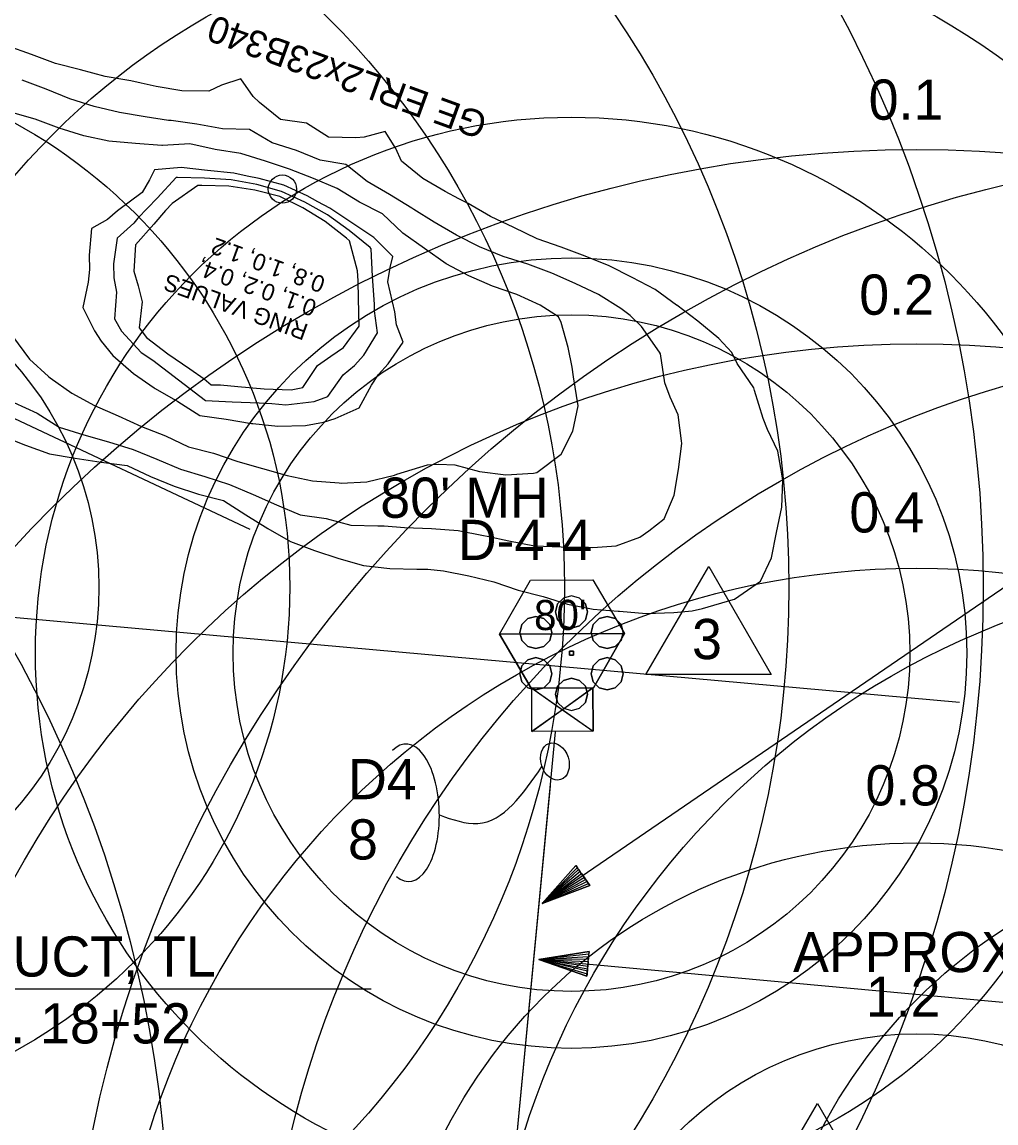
# Model space of a CAD drawing. Extents: x 1638506 to 1658005, y 834807 to 846788.
# Drawn here: x 1641616.9 to 1641907.6, y 842309.7 to 842638.4 of the extents above; entities that cross this region are included whole.
import ezdxf

# ---------------------------------------------------------------- set-up
doc = ezdxf.new("R2010")
doc.units = 0
for name, color, linetype in [('Default', 7, 'Continuous'), ('Old_Level_1', 7, 'Continuous'), ('Old_Level_2', 7, 'Continuous'), ('Old_Level_4', 7, 'Continuous'), ('Scratch_Level_0', 7, 'Continuous')]:
    doc.layers.add(name, color=color, linetype=linetype)

msp = doc.modelspace()

# ---------------------------------------------------------------- linework, layer by layer
at = {"layer": 'Default'}
for p, q in [((1642010.57, 842538.29), (1641772.14, 842375.26)), ((1641769.06, 842439.54), (1641787.43, 842426.69)), ((1641769.14, 842426.58), (1641787.35, 842439.65)), ((1641763.26, 842291.23), (1641776.21, 842426.53)), ((1641763.65, 842295.33), (1641774.67, 842410.42)), ((1641771.15, 842358.56), (1642042.57, 842333.49)), ((1641501.67, 842349.79), (1641721.14, 842349.79))]:
    msp.add_line(p, q, dxfattribs=at)
for points in [[(1641840.54, 842443.61), (1641803.15, 842443.61), (1641821.98, 842475.88)], [(1641759.43, 842455.63), (1641768.73, 842471.83), (1641787.31, 842471.94), (1641796.8, 842455.85)], [(1641759.43, 842455.63), (1641768.92, 842439.54), (1641787.5, 842439.65), (1641796.8, 842455.85)], [(1641759.43, 842455.63), (1641796.8, 842455.85), (1641787.5, 842439.65), (1641768.92, 842439.54)], [(1641769.06, 842439.54), (1641787.35, 842439.65), (1641787.43, 842426.69), (1641769.14, 842426.58)], [(1641778.25, 842433.11), (1641769.14, 842426.58), (1641769.06, 842439.54)], [(1641778.25, 842433.11), (1641787.43, 842426.69), (1641787.35, 842439.65)], [(1641872.96, 842283.3), (1641835.57, 842283.3), (1641854.4, 842315.57)]]:
    msp.add_lwpolyline(points, close=True, dxfattribs=at)
for points in [[(1641784.35, 842383.61), (1641784.77, 842383), (1641772.14, 842375.26), (1641785.16, 842382.43), (1641785.58, 842381.82), (1641772.14, 842375.26), (1641786, 842381.21), (1641786.41, 842380.6), (1641772.14, 842375.26), (1641782.23, 842386.63), (1641782.68, 842386.05), (1641772.14, 842375.26), (1641783.06, 842385.41), (1641783.52, 842384.83), (1641772.14, 842375.26), (1641783.94, 842384.22), (1641786.41, 842380.6), (1641782.23, 842386.63), (1641772.14, 842375.26), (1641786.41, 842380.6)], [(1641785.88, 842357.2), (1641785.81, 842356.46), (1641771.15, 842358.56), (1641785.75, 842355.78), (1641785.68, 842355.04), (1641771.15, 842358.56), (1641785.61, 842354.3), (1641785.54, 842353.57), (1641771.15, 842358.56), (1641786.17, 842360.89), (1641786.15, 842360.15), (1641771.15, 842358.56), (1641786.03, 842359.41), (1641786.02, 842358.67), (1641771.15, 842358.56), (1641785.95, 842357.94), (1641785.54, 842353.57), (1641786.17, 842360.89), (1641771.15, 842358.56), (1641785.54, 842353.57)]]:
    msp.add_lwpolyline(points, dxfattribs=at)
for start_param, end_param in [(1.570796, 3.572354), (5.884886, 7.853982)]:
    msp.add_ellipse((1641731.92, 842402.36), major_axis=(0.49, -20.52), ratio=0.466223, start_param=start_param, end_param=end_param, dxfattribs=at)
msp.add_ellipse((1641775.98, 842417.66), major_axis=(-1.72, 5.4), ratio=0.730797, dxfattribs=at)
msp.add_spline([(1641741.5, 842401.69), (1641752.96, 842399.12), (1641772.12, 842416.16)], degree=3, dxfattribs=at)
at = {"layer": 'Old_Level_1'}
for points in [[(1641610.87, 842514.93), (1641617.98, 842512.1), (1641625.17, 842509.48), (1641632.83, 842508.17), (1641640.56, 842507.04), (1641648.34, 842506.04), (1641655.27, 842502.71), (1641662.35, 842499.82), (1641669.64, 842497.48), (1641677.09, 842495.57), (1641683.69, 842491.34), (1641690.34, 842487.24), (1641697.05, 842483.32), (1641704.24, 842480.7), (1641711.51, 842478.3), (1641718.88, 842476.19), (1641726.67, 842475.23), (1641734.75, 842475.06), (1641738.1, 842475.05), (1641742.72, 842474.59), (1641750.33, 842473.12), (1641757.79, 842471.25), (1641765.05, 842468.83), (1641772.48, 842466.89), (1641779.79, 842464.61), (1641787.41, 842463.15), (1641794.86, 842462.54), (1641795.31, 842462.51), (1641803.22, 842461.86), (1641811.44, 842462.1), (1641816.97, 842462.63), (1641820.02, 842463.3), (1641829.15, 842466.01), (1641829.63, 842466.16), (1641837.32, 842471.5), (1641840.63, 842478.44), (1641842.1, 842486.05), (1641843.71, 842493.6), (1641843.98, 842501.65), (1641843.44, 842505.27), (1641842.5, 842510.32), (1641839.47, 842516.73), (1641838.17, 842520.04), (1641835.59, 842528.44), (1641835.33, 842529.22), (1641830.36, 842536.45), (1641828.78, 842539.74), (1641824.95, 842543.93), (1641818.68, 842549.09), (1641812.34, 842553.87), (1641812.29, 842553.9), (1641805.87, 842558.61), (1641799.01, 842562.13), (1641792.14, 842565.62), (1641785.06, 842568.55), (1641777.89, 842571.21), (1641770.65, 842573.68), (1641763.75, 842577.09), (1641756.78, 842580.32), (1641750.07, 842584.25), (1641747.27, 842585.69), (1641743.24, 842587.84), (1641736.52, 842591.75), (1641730.24, 842596.87), (1641728.54, 842600.65), (1641725.34, 842605.77), (1641719.06, 842604.1), (1641716.52, 842603.9), (1641708.44, 842604.08), (1641701.83, 842608.28), (1641694.06, 842609.31), (1641687.76, 842614.36), (1641685.94, 842616.15), (1641682.21, 842621.47), (1641676.46, 842619.6), (1641672.73, 842617.8), (1641664.63, 842617.92), (1641656.97, 842619.23), (1641652.51, 842620.18), (1641649.43, 842620.88), (1641641.76, 842622.18), (1641634.35, 842624.18), (1641626.87, 842626.01), (1641619.74, 842628.77), (1641612.53, 842631.35)], [(1641614.48, 842524.86), (1641621.44, 842521.61), (1641628.06, 842517.44), (1641635.38, 842515.18), (1641642.75, 842513.05), (1641650.09, 842510.85), (1641657.17, 842507.93), (1641664.22, 842504.94), (1641671.54, 842502.7), (1641678.84, 842500.38), (1641685.88, 842497.35), (1641692.89, 842494.25), (1641699.95, 842491.28), (1641707.7, 842490.21), (1641715.12, 842488.23), (1641723.18, 842488), (1641724.99, 842487.97), (1641731.13, 842487.47), (1641739.16, 842487.18), (1641747.1, 842486.61), (1641754.69, 842485.1), (1641755.79, 842484.9), (1641762.27, 842483.56), (1641769.88, 842482.09), (1641777.9, 842481.78), (1641785.98, 842481.61), (1641787.28, 842481.58), (1641794.29, 842482.07), (1641801.38, 842484.59), (1641804.05, 842486.52), (1641808.57, 842490.11), (1641811.63, 842497.14), (1641812.9, 842504.82), (1641813.91, 842512.59), (1641813.82, 842513.37), (1641812.74, 842521.16), (1641810.42, 842526.39), (1641808.82, 842530.72), (1641807.49, 842539.35), (1641807.18, 842539.85), (1641801.83, 842547.52), (1641798.42, 842550.79), (1641795.64, 842552.88), (1641789.04, 842557.11), (1641782.07, 842560.33), (1641775.07, 842563.47), (1641767.89, 842566.09), (1641760.59, 842568.43), (1641753.51, 842571.34), (1641746.62, 842574.78), (1641739.92, 842578.72), (1641733.88, 842582.42), (1641733.29, 842582.89), (1641726.63, 842586.96), (1641719.91, 842590.85), (1641713.6, 842595.88), (1641705.93, 842597.18), (1641698.84, 842600.07), (1641691.55, 842602.41), (1641684.84, 842606.35), (1641676.78, 842606.55), (1641669.12, 842607.89), (1641661.41, 842609.06), (1641660.66, 842609.07), (1641653.65, 842610.12), (1641645.98, 842611.41), (1641638.49, 842613.2), (1641631.2, 842615.53), (1641624.11, 842618.42), (1641616.92, 842621.03)], [(1641614.09, 842544.61), (1641619.2, 842537.82), (1641624.81, 842532.57), (1641625.3, 842532.21), (1641631.76, 842527.6), (1641638.58, 842523.98), (1641645.58, 842520.84), (1641652.57, 842517.68), (1641659.71, 842514.91), (1641666.64, 842511.61), (1641674.08, 842509.68), (1641681.33, 842507.22), (1641688.71, 842505.14), (1641696.09, 842503.04), (1641703.64, 842501.43), (1641711.56, 842500.82), (1641712.16, 842500.78), (1641719.84, 842501.19), (1641728.12, 842503.11), (1641728.8, 842503.45), (1641737.97, 842506.26), (1641741.26, 842506.47), (1641746.08, 842506.18), (1641753.52, 842504.26), (1641761.3, 842503.27), (1641769.63, 842503.78), (1641770.61, 842503.93), (1641777.85, 842509.43), (1641781.34, 842516.3), (1641782.96, 842523.86), (1641781.54, 842532.51), (1641781.14, 842535.42), (1641779.96, 842541.23), (1641777.86, 842548.77), (1641777.04, 842550.43), (1641771.6, 842553.92), (1641764.62, 842557.13), (1641757.38, 842559.61), (1641750.34, 842562.63), (1641743.51, 842566.24), (1641737.03, 842570.78), (1641730.58, 842575.44), (1641730.47, 842575.52), (1641724.51, 842581.13), (1641717.66, 842584.68), (1641710.98, 842588.69), (1641703.93, 842591.69), (1641696.8, 842594.47), (1641689.56, 842596.92), (1641682.23, 842599.15), (1641674.53, 842600.38), (1641667, 842602.06), (1641658.83, 842601.6), (1641658.69, 842601.6), (1641650.76, 842602.18), (1641642.87, 842602.87), (1641635.33, 842604.5), (1641627.99, 842606.71), (1641620.85, 842609.46), (1641613.45, 842611.48)], [(1641636.92, 842568.87), (1641637.07, 842564.56), (1641636.68, 842560.81), (1641635.11, 842553.24), (1641638.53, 842546.2), (1641640.52, 842543.14), (1641644.01, 842538.9), (1641650.19, 842533.51), (1641656.41, 842529.21), (1641656.7, 842529.03), (1641663.43, 842525.14), (1641670.03, 842520.92), (1641677.81, 842519.91), (1641685.46, 842518.56), (1641685.79, 842518.52), (1641693.33, 842517.81), (1641701.52, 842517.97), (1641706.93, 842518.96), (1641710.42, 842520.04), (1641717.56, 842523.23), (1641721.23, 842530.04), (1641723.34, 842533.17), (1641726.22, 842536.36), (1641730.73, 842542.86), (1641728.75, 842548.03), (1641728.18, 842551.93), (1641726.07, 842560.84), (1641726.83, 842565.14), (1641727.56, 842568.44), (1641721.94, 842574.06), (1641715.39, 842578.43), (1641708.85, 842582.85), (1641705.22, 842584.71), (1641702.05, 842586.5), (1641695.09, 842589.75), (1641687.67, 842591.74), (1641684.09, 842592.4), (1641680.1, 842593.31), (1641672.26, 842594.13), (1641664.43, 842595), (1641656.51, 842594.3), (1641654.95, 842591.31), (1641652.77, 842587.52), (1641645.43, 842582.05), (1641642.48, 842579.43), (1641637.64, 842576.75), (1641636.92, 842568.87)], [(1641644.18, 842566.23), (1641644.3, 842562.06), (1641645.09, 842557.75), (1641644.5, 842549.83), (1641646.63, 842546.1), (1641652.49, 842539.81), (1641655.95, 842537.52), (1641658.93, 842535.16), (1641665.31, 842530.3), (1641671.68, 842525.43), (1641679.68, 842525.06), (1641687.69, 842524.69), (1641691.49, 842524.58), (1641695.62, 842524.11), (1641704.14, 842525.17), (1641708.18, 842526.65), (1641712.82, 842533.1), (1641716.19, 842535.9), (1641718.97, 842539.01), (1641723.03, 842545.67), (1641722.13, 842552.23), (1641722.09, 842554.15), (1641721.53, 842562.5), (1641721.18, 842570.76), (1641720.86, 842571.09), (1641714.56, 842576.16), (1641708.14, 842580.88), (1641701.37, 842584.64), (1641694.38, 842587.82), (1641686.99, 842589.88), (1641679.38, 842591.35), (1641671.43, 842591.86), (1641663.35, 842592.02), (1641662.89, 842591.98), (1641657.31, 842585.87), (1641651.52, 842579.84), (1641650.25, 842578.39), (1641645.34, 842573.94), (1641644.18, 842566.23)], [(1641650.28, 842564), (1641651.57, 842559.65), (1641652.81, 842554.94), (1641651.92, 842547.13), (1641654.11, 842544.28), (1641660.46, 842539.36), (1641666.97, 842534.87), (1641671.25, 842531.95), (1641673.4, 842530.16), (1641676.19, 842530.15), (1641681.35, 842529.64), (1641689.22, 842528.89), (1641697.25, 842528.59), (1641700.76, 842529.35), (1641705.1, 842535.91), (1641709.08, 842538.72), (1641712.86, 842541.23), (1641717.58, 842547.65), (1641717.32, 842555.89), (1641717.26, 842561.21), (1641717.06, 842564.12), (1641714.65, 842573.14), (1641713.73, 842573.89), (1641707.42, 842578.92), (1641700.76, 842582.99), (1641693.84, 842586.33), (1641686.39, 842588.22), (1641678.67, 842589.38), (1641670.6, 842589.59), (1641669.42, 842589.6), (1641661.78, 842584.24), (1641659.75, 842582.14), (1641656.28, 842578.1), (1641650.79, 842571.96), (1641650.28, 842564)]]:
    msp.add_lwpolyline(points, dxfattribs=at)
for centre, radius in [((1641295.68, 842272.71), 365), ((1641995.81, 842234.97), 365), ((1641694.65, 842588.56), 4.21), ((1641995.81, 842234.97), 307), ((1641995.81, 842234.97), 240), ((1641995.81, 842234.97), 158), ((1641995.81, 842234.97), 101)]:
    msp.add_circle(centre, radius, dxfattribs=at)
at = {"layer": 'Old_Level_2'}
for p, q in [((1641448.99, 842597.9), (1641684.96, 842487.06)), ((1641289.11, 842489.79), (1641896.79, 842435.41))]:
    msp.add_line(p, q, dxfattribs=at)
at = {"layer": 'Old_Level_4'}
for centre, radius in [((1641538.84, 842469.72), 365), ((1641538.84, 842469.72), 307), ((1641538.84, 842469.72), 240), ((1641538.84, 842469.72), 158), ((1641883.97, 842235.35), 365), ((1641538.84, 842469.72), 101), ((1641883.97, 842235.35), 307), ((1641883.97, 842235.35), 240), ((1641883.97, 842235.35), 158), ((1641883.97, 842235.35), 101)]:
    msp.add_circle(centre, radius, dxfattribs=at)
at = {"layer": 'Scratch_Level_0'}
for points in [[(1641776.77, 842459.91), (1641778.53, 842458.15), (1641780.93, 842457.51), (1641783.33, 842458.15), (1641785.08, 842459.91), (1641785.73, 842462.31), (1641785.08, 842464.71), (1641783.33, 842466.47), (1641780.93, 842467.11), (1641778.53, 842466.47), (1641776.77, 842464.71), (1641776.13, 842462.31)], [(1641776.77, 842459.91), (1641778.53, 842458.15), (1641780.93, 842457.51), (1641783.33, 842458.15), (1641785.08, 842459.91), (1641785.73, 842462.31), (1641785.08, 842464.71), (1641783.33, 842466.47), (1641780.93, 842467.11), (1641778.53, 842466.47), (1641776.77, 842464.71), (1641776.13, 842462.31)], [(1641778.53, 842466.47), (1641776.77, 842464.71), (1641776.77, 842464.71)], [(1641785.08, 842464.71), (1641783.33, 842466.47), (1641783.33, 842466.47)], [(1641776.77, 842464.71), (1641776.13, 842462.31), (1641776.13, 842462.31)], [(1641785.73, 842462.31), (1641785.08, 842464.71), (1641785.08, 842464.71)], [(1641770.27, 842451.36), (1641772.67, 842452), (1641774.43, 842453.76), (1641775.07, 842456.16), (1641774.43, 842458.56), (1641772.67, 842460.32), (1641770.27, 842460.96), (1641767.87, 842460.32), (1641766.12, 842458.56), (1641765.47, 842456.16), (1641766.12, 842453.76), (1641767.87, 842452)], [(1641770.27, 842451.36), (1641772.67, 842452), (1641774.43, 842453.76), (1641775.07, 842456.16), (1641774.43, 842458.56), (1641772.67, 842460.32), (1641770.27, 842460.96), (1641767.87, 842460.32), (1641766.12, 842458.56), (1641765.47, 842456.16), (1641766.12, 842453.76), (1641767.87, 842452)], [(1641767.87, 842460.32), (1641766.12, 842458.56), (1641766.12, 842458.56)], [(1641770.27, 842460.96), (1641767.87, 842460.32), (1641767.87, 842460.32)], [(1641772.67, 842460.32), (1641770.27, 842460.96), (1641770.27, 842460.96)], [(1641774.43, 842458.56), (1641772.67, 842460.32), (1641772.67, 842460.32)], [(1641776.13, 842462.31), (1641776.77, 842459.91), (1641776.77, 842459.91)], [(1641776.77, 842459.91), (1641778.53, 842458.15), (1641778.53, 842458.15)], [(1641783.33, 842458.15), (1641785.08, 842459.91), (1641785.08, 842459.91)], [(1641785.08, 842459.91), (1641785.73, 842462.31), (1641785.73, 842462.31)], [(1641787.42, 842458.56), (1641786.78, 842456.16), (1641787.42, 842453.76), (1641789.18, 842452), (1641791.58, 842451.36), (1641793.98, 842452), (1641795.74, 842453.76), (1641796.38, 842456.16), (1641795.74, 842458.56), (1641793.98, 842460.32), (1641791.58, 842460.96), (1641789.18, 842460.32)], [(1641787.42, 842458.56), (1641786.78, 842456.16), (1641787.42, 842453.76), (1641789.18, 842452), (1641791.58, 842451.36), (1641793.98, 842452), (1641795.74, 842453.76), (1641796.38, 842456.16), (1641795.74, 842458.56), (1641793.98, 842460.32), (1641791.58, 842460.96), (1641789.18, 842460.32)], [(1641789.18, 842460.32), (1641787.42, 842458.56), (1641787.42, 842458.56)], [(1641791.58, 842460.96), (1641789.18, 842460.32), (1641789.18, 842460.32)], [(1641793.98, 842460.32), (1641791.58, 842460.96), (1641791.58, 842460.96)], [(1641795.74, 842458.56), (1641793.98, 842460.32), (1641793.98, 842460.32)], [(1641766.12, 842458.56), (1641765.47, 842456.16), (1641765.47, 842456.16)], [(1641775.07, 842456.16), (1641774.43, 842458.56), (1641774.43, 842458.56)], [(1641778.53, 842458.15), (1641780.93, 842457.51), (1641780.93, 842457.51)], [(1641780.93, 842457.51), (1641783.33, 842458.15), (1641783.33, 842458.15)], [(1641787.42, 842458.56), (1641786.78, 842456.16), (1641786.78, 842456.16)], [(1641796.38, 842456.16), (1641795.74, 842458.56), (1641795.74, 842458.56)], [(1641765.47, 842456.16), (1641766.12, 842453.76), (1641766.12, 842453.76)], [(1641766.12, 842453.76), (1641767.87, 842452), (1641767.87, 842452)], [(1641772.67, 842452), (1641774.43, 842453.76), (1641774.43, 842453.76)], [(1641774.43, 842453.76), (1641775.07, 842456.16), (1641775.07, 842456.16)], [(1641786.78, 842456.16), (1641787.42, 842453.76), (1641787.42, 842453.76)], [(1641787.42, 842453.76), (1641789.18, 842452), (1641789.18, 842452)], [(1641793.98, 842452), (1641795.74, 842453.76), (1641795.74, 842453.76)], [(1641795.74, 842453.76), (1641796.38, 842456.16), (1641796.38, 842456.16)], [(1641767.87, 842452), (1641770.27, 842451.36), (1641770.27, 842451.36)], [(1641770.27, 842451.36), (1641772.67, 842452), (1641772.67, 842452)], [(1641780.3, 842449.38), (1641781.55, 842449.38), (1641781.55, 842450.63), (1641780.3, 842450.63)], [(1641780.3, 842449.38), (1641781.55, 842449.38), (1641781.55, 842450.63), (1641780.3, 842450.63)], [(1641781.55, 842450.63), (1641780.3, 842450.63), (1641780.3, 842450.63), (1641781.55, 842450.63)], [(1641780.3, 842450.63), (1641780.3, 842449.38), (1641780.3, 842449.38), (1641780.3, 842450.63)], [(1641781.55, 842449.38), (1641781.55, 842450.63), (1641781.55, 842450.63), (1641781.55, 842449.38)], [(1641789.18, 842452), (1641791.58, 842451.36), (1641791.58, 842451.36)], [(1641791.58, 842451.36), (1641793.98, 842452), (1641793.98, 842452)], [(1641774.43, 842441.46), (1641775.07, 842443.86), (1641774.43, 842446.26), (1641772.67, 842448.02), (1641770.27, 842448.66), (1641767.87, 842448.02), (1641766.12, 842446.26), (1641765.47, 842443.86), (1641766.12, 842441.46), (1641767.87, 842439.7), (1641770.27, 842439.06), (1641772.67, 842439.7)], [(1641774.43, 842441.46), (1641775.07, 842443.86), (1641774.43, 842446.26), (1641772.67, 842448.02), (1641770.27, 842448.66), (1641767.87, 842448.02), (1641766.12, 842446.26), (1641765.47, 842443.86), (1641766.12, 842441.46), (1641767.87, 842439.7), (1641770.27, 842439.06), (1641772.67, 842439.7)], [(1641767.87, 842448.02), (1641766.12, 842446.26), (1641766.12, 842446.26)], [(1641770.27, 842448.66), (1641767.87, 842448.02), (1641767.87, 842448.02)], [(1641772.67, 842448.02), (1641770.27, 842448.66), (1641770.27, 842448.66)], [(1641774.43, 842446.26), (1641772.67, 842448.02), (1641772.67, 842448.02)], [(1641780.3, 842449.38), (1641781.55, 842449.38), (1641781.55, 842449.38), (1641780.3, 842449.38)], [(1641791.58, 842448.66), (1641789.18, 842448.02), (1641787.42, 842446.26), (1641786.78, 842443.86), (1641787.42, 842441.46), (1641789.18, 842439.7), (1641791.58, 842439.06), (1641793.98, 842439.7), (1641795.74, 842441.46), (1641796.38, 842443.86), (1641795.74, 842446.26), (1641793.98, 842448.02)], [(1641791.58, 842448.66), (1641789.18, 842448.02), (1641787.42, 842446.26), (1641786.78, 842443.86), (1641787.42, 842441.46), (1641789.18, 842439.7), (1641791.58, 842439.06), (1641793.98, 842439.7), (1641795.74, 842441.46), (1641796.38, 842443.86), (1641795.74, 842446.26), (1641793.98, 842448.02)], [(1641789.18, 842448.02), (1641787.42, 842446.26), (1641787.42, 842446.26)], [(1641791.58, 842448.66), (1641789.18, 842448.02), (1641789.18, 842448.02)], [(1641793.98, 842448.02), (1641791.58, 842448.66), (1641791.58, 842448.66)], [(1641795.74, 842446.26), (1641793.98, 842448.02), (1641793.98, 842448.02)], [(1641766.12, 842446.26), (1641765.47, 842443.86), (1641765.47, 842443.86)], [(1641765.47, 842443.86), (1641766.12, 842441.46), (1641766.12, 842441.46)], [(1641775.07, 842443.86), (1641774.43, 842446.26), (1641774.43, 842446.26)], [(1641774.43, 842441.46), (1641775.07, 842443.86), (1641775.07, 842443.86)], [(1641787.42, 842446.26), (1641786.78, 842443.86), (1641786.78, 842443.86)], [(1641786.78, 842443.86), (1641787.42, 842441.46), (1641787.42, 842441.46)], [(1641796.38, 842443.86), (1641795.74, 842446.26), (1641795.74, 842446.26)], [(1641795.74, 842441.46), (1641796.38, 842443.86), (1641796.38, 842443.86)], [(1641766.12, 842441.46), (1641767.87, 842439.7), (1641767.87, 842439.7)], [(1641772.67, 842439.7), (1641774.43, 842441.46), (1641774.43, 842441.46)], [(1641785.08, 842440.11), (1641783.33, 842441.87), (1641780.93, 842442.51), (1641778.53, 842441.87), (1641776.77, 842440.11), (1641776.13, 842437.71), (1641776.77, 842435.31), (1641778.53, 842433.55), (1641780.93, 842432.91), (1641783.33, 842433.55), (1641785.08, 842435.31), (1641785.73, 842437.71)], [(1641785.08, 842440.11), (1641783.33, 842441.87), (1641780.93, 842442.51), (1641778.53, 842441.87), (1641776.77, 842440.11), (1641776.13, 842437.71), (1641776.77, 842435.31), (1641778.53, 842433.55), (1641780.93, 842432.91), (1641783.33, 842433.55), (1641785.08, 842435.31), (1641785.73, 842437.71)], [(1641776.77, 842440.11), (1641776.13, 842437.71), (1641776.13, 842437.71)], [(1641778.53, 842441.87), (1641776.77, 842440.11), (1641776.77, 842440.11)], [(1641780.93, 842442.51), (1641778.53, 842441.87), (1641778.53, 842441.87)], [(1641783.33, 842441.87), (1641780.93, 842442.51), (1641780.93, 842442.51)], [(1641785.08, 842440.11), (1641783.33, 842441.87), (1641783.33, 842441.87)], [(1641785.73, 842437.71), (1641785.08, 842440.11), (1641785.08, 842440.11)], [(1641787.42, 842441.46), (1641789.18, 842439.7), (1641789.18, 842439.7)], [(1641793.98, 842439.7), (1641795.74, 842441.46), (1641795.74, 842441.46)], [(1641767.87, 842439.7), (1641770.27, 842439.06), (1641770.27, 842439.06)], [(1641770.27, 842439.06), (1641772.67, 842439.7), (1641772.67, 842439.7)], [(1641776.13, 842437.71), (1641776.77, 842435.31), (1641776.77, 842435.31)], [(1641785.08, 842435.31), (1641785.73, 842437.71), (1641785.73, 842437.71)], [(1641789.18, 842439.7), (1641791.58, 842439.06), (1641791.58, 842439.06)], [(1641791.58, 842439.06), (1641793.98, 842439.7), (1641793.98, 842439.7)], [(1641776.77, 842435.31), (1641778.53, 842433.55), (1641778.53, 842433.55)], [(1641783.33, 842433.55), (1641785.08, 842435.31), (1641785.08, 842435.31)]]:
    msp.add_lwpolyline(points, close=True, dxfattribs=at)
for radius in [297, 264, 219, 160, 118, 101]:
    msp.add_circle((1641780.93, 842450.01), radius, dxfattribs=at)

# ---------------------------------------------------------------- texts
at = {"layer": 'Default'}
for s, p in [('D-4-4', (1641747, 842477.82)), ('3', (1641816.92, 842448.22)), ('D4', (1641714.23, 842406.4)), ('8', (1641714.23, 842388.4)), ('4" ELEC. DUCT, TL', (1641532.62, 842353.44)), ('APPROX. 300 FT', (1641847.06, 842354.77)), ('-RPD- STA. 18+52', (1641533.16, 842333.48))]:
    msp.add_text(s, height=12, dxfattribs=at).set_placement(p)
msp.add_text("80'", height=9, rotation=0.3328, dxfattribs=at).set_placement((1641769.78, 842456.87))
at = {"layer": 'Old_Level_1'}
for s, height, p in [('GE ERL2x23B340', 8, (1641756.4, 842610.8)), ('0.8, 1.0, 1.2', 5, (1641707.82, 842562.11)), ('0.1, 0.2, 0.4,', 5, (1641705.26, 842555.06)), ('RING VALUES', 5, (1641702.69, 842548.01))]:
    msp.add_text(s, height=height, rotation=160, dxfattribs=at).set_placement(p)
at = {"layer": 'Old_Level_4'}
for s, p in [('0.1', (1641869.63, 842609.27)), ('0.2', (1641866.83, 842551.05)), ('0.4', (1641863.88, 842486.04)), ('0.8', (1641868.67, 842404.54)), ('1.2', (1641868.77, 842341.45))]:
    msp.add_text(s, height=12, dxfattribs=at).set_placement(p)
at = {"layer": 'Scratch_Level_0'}
msp.add_text("80' MH", height=12, dxfattribs=at).set_placement((1641723.86, 842490.42))

doc.saveas('drawing.dxf')
